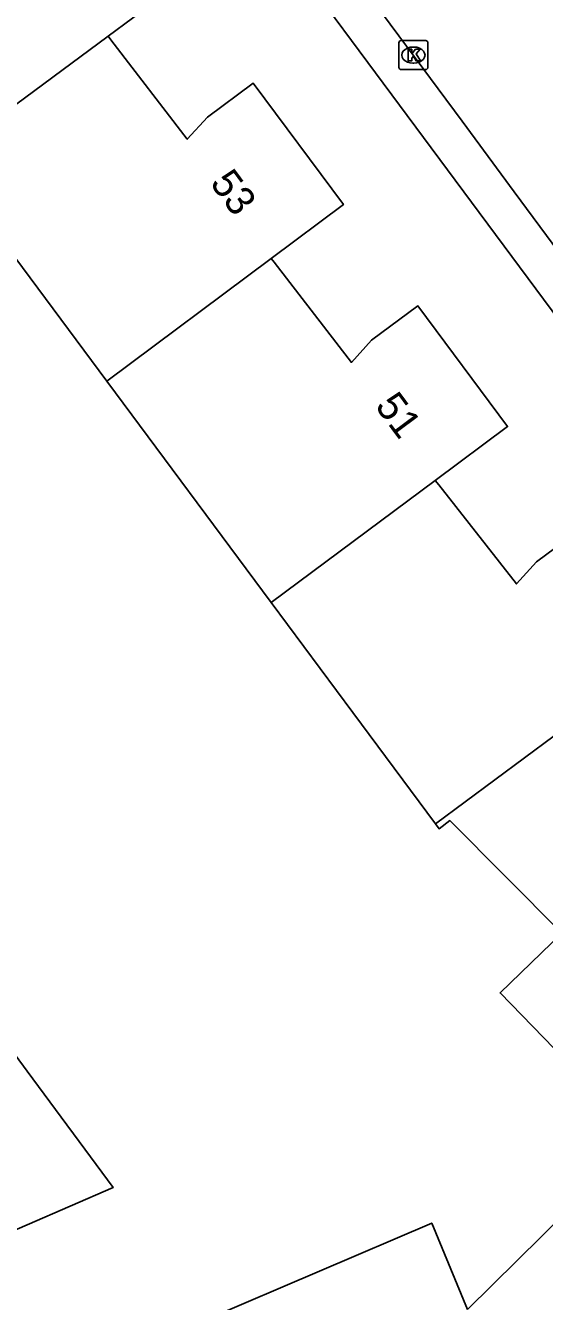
# Model space of a CAD drawing. Extents: x 157767 to 159171, y 387842 to 389425.
# Drawn here: x 158194.7 to 158212.64, y 388753.46 to 388797.56 of the extents above; entities that cross this region are included whole.
import ezdxf

# ---------------------------------------------------------------- set-up
doc = ezdxf.new("R2010")
doc.units = 0
for name, color, linetype in [('IMGEO_Kolk', 7, 'Continuous'), ('IMGEO_Pand', 7, 'Continuous'), ('IMGEO_Pand_nummerreeks', 7, 'Continuous'), ('IMGEO_Rijbaan_lokaal_open', 7, 'Continuous'), ('IMGEO_Voetpad_open', 7, 'Continuous')]:
    doc.layers.add(name, color=color, linetype=linetype)

msp = doc.modelspace()

# ---------------------------------------------------------------- linework, layer by layer
at = {"layer": 'IMGEO_Kolk'}
for p, q in [((158207.609, 388796.109), (158207.609, 388796.961)), ((158207.684, 388797.035), (158208.536, 388797.035)), ((158208.097, 388796.815), (158208.122, 388796.815)), ((158208.61, 388796.961), (158208.61, 388796.109)), ((158208.536, 388796.035), (158207.684, 388796.035)), ((158208.12, 388796.255), (158208.095, 388796.255))]:
    msp.add_line(p, q, dxfattribs=at)
for points in [[(158207.609, 388796.109), (158207.609, 388796.961)], [(158207.684, 388797.035), (158208.536, 388797.035)], [(158208.61, 388796.961), (158208.61, 388796.109)], [(158207.93, 388796.735), (158208.053, 388796.735), (158208.053, 388796.584), (158208.183, 388796.735), (158208.347, 388796.735), (158208.201, 388796.584), (158208.354, 388796.335), (158208.202, 388796.335), (158208.117, 388796.499), (158208.053, 388796.432), (158208.053, 388796.335), (158207.93, 388796.335), (158207.93, 388796.735)], [(158208.536, 388796.035), (158207.684, 388796.035)]]:
    msp.add_lwpolyline(points, dxfattribs=at)
for centre, start, end in [((158207.686, 388796.959), 91.552, 178.448), ((158207.686, 388796.959), 91.552, 178.448), ((158208.534, 388796.959), 1.552, 88.448), ((158208.534, 388796.959), 1.552, 88.448), ((158207.686, 388796.111), 181.552, 268.448), ((158207.686, 388796.111), 181.552, 268.448), ((158208.534, 388796.111), 271.552, 358.448), ((158208.534, 388796.111), 271.552, 358.448)]:
    msp.add_arc(centre, 0.0765, start, end, dxfattribs=at)
for centre, major_axis, ratio, start_param, end_param in [((158208.096, 388796.535), (-0.387, 0.002), 0.722429, 4.712389, 7.853982), ((158208.121, 388796.535), (-0.39, 0.002), 0.717154, 1.570796, 4.712389)]:
    msp.add_ellipse(centre, major_axis=major_axis, ratio=ratio, start_param=start_param, end_param=end_param, dxfattribs=at)
at = {"layer": 'IMGEO_Pand'}
for points in [[(158191.043, 388804.245), (158193.097, 388801.458), (158193.887, 388800.724), (158194.506, 388801.432), (158196.119, 388802.63), (158199.238, 388798.431), (158197.556, 388797.187)], [(158197.556, 388797.187), (158191.811, 388792.94)], [(158197.556, 388797.187), (158197.653, 388797.061), (158200.291, 388793.625), (158200.989, 388794.393), (158202.57, 388795.568), (158205.688, 388791.368), (158203.193, 388789.506)], [(158197.511, 388785.266), (158191.939, 388792.768), (158191.811, 388792.94)], [(158197.511, 388785.266), (158203.193, 388789.506)], [(158203.193, 388789.506), (158203.295, 388789.375), (158205.97, 388785.916), (158206.661, 388786.679), (158208.266, 388787.871), (158211.366, 388783.697), (158208.867, 388781.837)], [(158203.193, 388777.615), (158197.511, 388785.266)], [(158208.867, 388781.837), (158203.193, 388777.615)], [(158215.029, 388774.529), (158217.065, 388776.038), (158213.964, 388780.214), (158212.359, 388779.022), (158211.668, 388778.26), (158208.984, 388781.688), (158208.867, 388781.837)], [(158203.193, 388777.615), (158206.015, 388773.815), (158208.873, 388769.965)], [(158208.873, 388769.965), (158215.029, 388774.529)], [(158208.873, 388769.965), (158208.996, 388769.8), (158209.374, 388770.081), (158213.234, 388766.197), (158211.106, 388764.13), (158215.981, 388759.107)], [(158185.06, 388764.409), (158190.755, 388766.862), (158194.764, 388761.425), (158197.732, 388757.4), (158193.263, 388755.469), (158193.856, 388754.097), (158190.364, 388752.593), (158190.76, 388751.674), (158188.28, 388750.606), (158187.884, 388751.524), (158186.507, 388750.931), (158184.529, 388755.523), (158182.754, 388759.647), (158180.658, 388758.744), (158178.898, 388762.855), (158184.666, 388765.325), (158185.06, 388764.409)]]:
    msp.add_lwpolyline(points, dxfattribs=at)
at = {"layer": 'IMGEO_Rijbaan_lokaal_open'}
msp.add_lwpolyline([(158217.764, 388783.504), (158217.385, 388783.991), (158215.572, 388786.44), (158211.597, 388791.81), (158209.792, 388794.247), (158205.943, 388799.447), (158204.15, 388801.869), (158200.206, 388807.195), (158196.608, 388812.055), (158193.804, 388815.843), (158192.803, 388817.19), (158186.144, 388826.156), (158184.709, 388828.089), (158182.272, 388831.371), (158180.005, 388834.424), (158179.41, 388835.226), (158177.125, 388838.302), (158173.681, 388842.941)], dxfattribs=at)
at = {"layer": 'IMGEO_Voetpad_open'}
for points in [[(158189.191, 388816.451), (158191.896, 388815.985), (158192.648, 388814.972), (158218.714, 388779.875)], [(158215.981, 388759.107), (158209.98, 388753.187)], [(158209.98, 388753.187), (158208.741, 388756.173), (158200.983, 388752.851), (158194.387, 388750), (158185.972, 388746.363), (158187.619, 388742.643), (158165.563, 388733.146)]]:
    msp.add_lwpolyline(points, dxfattribs=at)

# ---------------------------------------------------------------- texts
at = {"layer": 'IMGEO_Pand_nummerreeks'}
for s, rotation, p in [('53', 306.5889, (158201.055, 388792.105)), ('51', 306.6003, (158206.758, 388784.402))]:
    msp.add_text(s, height=1, rotation=rotation, dxfattribs=at).set_placement(p)

doc.saveas('drawing.dxf')
